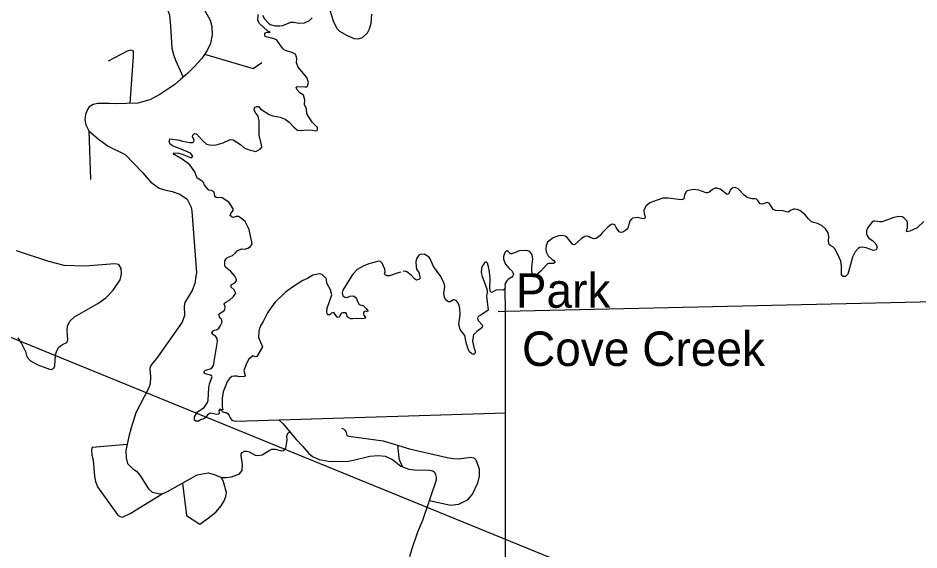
# Model space of a CAD drawing. Extents: x 1212896 to 1368412, y 378476 to 478763.
# Drawn here: x 1263202 to 1274256, y 408479 to 414998 of the extents above; entities that cross this region are included whole.
import ezdxf

# ---------------------------------------------------------------- set-up
doc = ezdxf.new("R2010")
doc.units = 0
for name, color, linetype in [('Level 31', 7, 'Continuous'), ('Level 32', 7, 'Continuous'), ('Level 45', 7, 'Continuous'), ('Level 46', 7, 'Continuous'), ('Level 5', 7, 'Continuous'), ('Level 60', 7, 'Continuous'), ('Level 7', 7, 'Continuous'), ('Level 9', 7, 'Continuous'), ('R_Draft', 7, 'Continuous')]:
    doc.layers.add(name, color=color, linetype=linetype)

msp = doc.modelspace()

# ---------------------------------------------------------------- linework, layer by layer
at = {"layer": 'Level 31'}
for points in [[(1265465, 415139), (1265558, 414972), (1265580, 414894), (1265583, 414791), (1265564, 414685), (1265521, 414599), (1265456, 414504), (1265365, 414399), (1265287, 414323), (1265195, 414246), (1265128, 414184), (1264944, 414060), (1264819, 413996), (1264672, 413955), (1264396, 413947), (1264326, 413952), (1264182, 413951), (1264125, 413938), (1264074, 413908), (1264053, 413878), (1264030, 413818), (1264021, 413752), (1264035, 413688), (1264073, 413617), (1264190, 413512), (1264308, 413426), (1264517, 413324), (1264729, 413106), (1264830, 412985), (1264933, 412912), (1265001, 412892), (1265092, 412873), (1265187, 412838), (1265278, 412779), (1265327, 412680), (1265336, 412631), (1265392, 411874), (1265382, 411833)], [(1265382, 411833), (1265370, 411745), (1265339, 411658), (1265247, 411513), (1265242, 411467), (1265244, 411351), (1265216, 411272), (1264912, 410841), (1264842, 410757), (1264827, 410733), (1264821, 410705), (1264829, 410599), (1264824, 410511), (1264805, 410458), (1264649, 410160), (1264589, 409978), (1264561, 409869), (1264527, 409699), (1264528, 409607), (1264547, 409539), (1264610, 409475), (1264654, 409444), (1264705, 409383), (1264805, 409230), (1264850, 409186), (1264925, 409172), (1264969, 409169), (1265038, 409196), (1265399, 409399), (1265535, 409426), (1265608, 409403), (1265698, 409368), (1265756, 409368), (1265823, 409376), (1265921, 409413), (1265954, 409452), (1265958, 409526), (1265941, 409638), (1265942, 409655), (1265952, 409673), (1265980, 409688), (1266002, 409692), (1266040, 409681), (1266112, 409639), (1266153, 409637), (1266196, 409645), (1266282, 409698), (1266318, 409713), (1266358, 409716), (1266435, 409693), (1266464, 409700), (1266487, 409725), (1266503, 409824), (1266501, 409873), (1266514, 409909), (1266536, 409926)], [(1266403, 410074), (1266454, 410024), (1266613, 409835), (1266695, 409749), (1266772, 409660), (1266814, 409624), (1266898, 409586), (1267032, 409565), (1267253, 409569), (1267319, 409579), (1267517, 409630), (1267620, 409635), (1267706, 409630), (1267798, 409589), (1267898, 409505), (1267996, 409468), (1268068, 409460), (1268250, 409459), (1268292, 409450), (1268312, 409432), (1268325, 409405), (1268333, 409371), (1268331, 409334), (1268166, 408840), (1268102, 408699), (1268032, 408495), (1268004, 408394)]]:
    msp.add_lwpolyline(points, dxfattribs=at)
at = {"layer": 'Level 32'}
for points in [[(1264942, 415255), (1265006, 415172), (1265042, 415095), (1265061, 415035), (1265075, 414902), (1265091, 414630), (1265110, 414553), (1265136, 414483), (1265230, 414275)], [(1264311, 414474), (1264547, 414596), (1264590, 414610), (1264614, 414595), (1264614, 414532), (1264576, 413952)], [(1264073, 413617), (1264090, 413020)], [(1264541, 409772), (1264113, 409734), (1264104, 409706), (1264109, 409641), (1264123, 409581), (1264140, 409381), (1264154, 409318), (1264176, 409252), (1264428, 408905), (1264456, 408890), (1264486, 408883), (1264578, 408926), (1264969, 409169)], [(1265220, 409298), (1265270, 408903), (1265431, 408794), (1265535, 408869), (1265628, 408942), (1265694, 409020), (1265732, 409080), (1265753, 409134), (1265759, 409183), (1265724, 409313), (1265698, 409368)]]:
    msp.add_lwpolyline(points, dxfattribs=at)
at = {"layer": 'Level 45'}
for points in [[(1265490, 414555), (1266088, 414378), (1266193, 414454)], [(1267172, 409970), (1267195, 409962), (1267211, 409949), (1267223, 409933), (1267237, 409883), (1267262, 409873), (1267684, 409815), (1268006, 409717), (1268468, 409612), (1268539, 409601), (1268605, 409598), (1268758, 409616), (1268795, 409607), (1268818, 409584), (1268858, 409473), (1268858, 409383), (1268839, 409296), (1268780, 409169), (1268711, 409088), (1268605, 409035), (1268511, 409024), (1268247, 409080)], [(1267856, 409762), (1267876, 409610), (1267888, 409568), (1267918, 409497)]]:
    msp.add_lwpolyline(points, dxfattribs=at)
at = {"layer": 'Level 46'}
msp.add_lwpolyline([(1263201, 411081), (1263244, 411011), (1263292, 410912), (1263312, 410848), (1263357, 410796), (1263444, 410750), (1263587, 410696), (1263611, 410692), (1263641, 410707), (1263655, 410734), (1263663, 410870), (1263679, 410921), (1263703, 410963), (1263746, 410998), (1263802, 411023), (1263815, 411053), (1263807, 411170), (1263808, 411221), (1263839, 411285), (1263897, 411338), (1264182, 411498), (1264278, 411570), (1264371, 411664), (1264457, 411790), (1264471, 411865), (1264468, 411928), (1264438, 411978), (1264390, 411986), (1264028, 411956), (1263769, 411966), (1263582, 412013), (1263183, 412145)], dxfattribs=at)
at = {"layer": 'Level 5'}
for points in [[(1274449, 411522), (1269181, 411401), (1269094, 411398)], [(1269182, 406131), (1269181, 410159)]]:
    msp.add_lwpolyline(points, dxfattribs=at)
at = {"layer": 'Level 60'}
msp.add_spline([(1275538, 388463), (1274493, 424373), (1274106, 437641)], degree=3, dxfattribs=at)
at = {"layer": 'Level 7'}
for points in [[(1269181, 410159), (1269181, 411401), (1269177, 411692)], [(1265680, 410203), (1265714, 410174), (1265727, 410166), (1265742, 410164), (1265754, 410163), (1265766, 410159), (1265779, 410148), (1265789, 410135), (1265794, 410122), (1265798, 410114), (1265807, 410097), (1265818, 410082), (1265827, 410072), (1265850, 410063), (1265880, 410058), (1269181, 410159)]]:
    msp.add_lwpolyline(points, dxfattribs=at)
at = {"layer": 'Level 9'}
for points in [[(1267009, 415160), (1267067, 414965), (1267115, 414870), (1267145, 414837), (1267239, 414786), (1267327, 414748), (1267378, 414743), (1267429, 414761), (1267488, 414817), (1267513, 414867), (1267536, 414935), (1267543, 415045)], [(1265359, 413486), (1265365, 413502), (1265342, 413546), (1265349, 413561), (1265369, 413582), (1265394, 413579), (1265464, 413496), (1265513, 413454), (1265573, 413440), (1265633, 413443), (1265719, 413470), (1265806, 413511), (1265841, 413505), (1265933, 413449), (1265978, 413409), (1266039, 413383), (1266119, 413363), (1266176, 413396), (1266194, 413417), (1266191, 413446), (1266160, 413564), (1266159, 413735), (1266147, 413796), (1266113, 413846), (1266100, 413874), (1266105, 413900), (1266131, 413914), (1266154, 413913), (1266180, 413881), (1266283, 413817), (1266329, 413798), (1266417, 413782), (1266481, 413760), (1266530, 413723), (1266587, 413661), (1266632, 413624), (1266672, 413619), (1266747, 413629), (1266815, 413625), (1266855, 413614), (1266875, 413626), (1266875, 413656), (1266812, 413721), (1266746, 413823), (1266740, 413884), (1266719, 413939), (1266721, 413997), (1266704, 414052), (1266659, 414083), (1266625, 414120), (1266616, 414149), (1266625, 414159), (1266720, 414155), (1266746, 414157), (1266754, 414163), (1266766, 414210), (1266744, 414270), (1266638, 414395), (1266618, 414448), (1266622, 414497), (1266610, 414551), (1266574, 414571), (1266470, 414606), (1266446, 414630), (1266379, 414726), (1266365, 414737), (1266315, 414753), (1266258, 414763), (1266235, 414773), (1266229, 414788), (1266231, 414806), (1266239, 414815), (1266258, 414824), (1266276, 414820), (1266294, 414825), (1266268, 414839), (1266166, 414930), (1266145, 414969)], [(1266145, 414969), (1266148, 415042)], [(1266202, 415035), (1266227, 414990), (1266274, 414934), (1266296, 414920), (1266358, 414902), (1266413, 414901), (1266452, 414906), (1266550, 414948), (1266587, 414946), (1266647, 414935), (1266719, 414939), (1266778, 414968), (1266813, 414999)], [(1265752, 411517), (1265796, 411542), (1265845, 411585), (1265874, 411625), (1265856, 411666), (1265816, 411700), (1265818, 411730), (1265863, 411754), (1265883, 411776), (1265881, 411793), (1265863, 411833), (1265815, 411891), (1265747, 411946), (1265740, 411962), (1265739, 412023), (1265754, 412049), (1265772, 412064), (1265834, 412089), (1265872, 412119), (1265892, 412144), (1265945, 412169), (1265985, 412164), (1266020, 412178), (1266054, 412197), (1266073, 412231), (1266037, 412405), (1265987, 412503), (1265933, 412551), (1265907, 412565), (1265879, 412564), (1265845, 412554), (1265828, 412559), (1265805, 412577), (1265815, 412604), (1265841, 412641), (1265840, 412661), (1265815, 412705), (1265787, 412742), (1265705, 412793), (1265634, 412799), (1265616, 412813), (1265614, 412849), (1265605, 412867), (1265578, 412885), (1265545, 412889), (1265490, 412948), (1265479, 412981), (1265460, 412997), (1265402, 413034), (1265372, 413114), (1265309, 413199), (1265217, 413267), (1265118, 413326), (1265110, 413338), (1265113, 413347), (1265171, 413342), (1265217, 413330), (1265320, 413288), (1265334, 413290), (1265346, 413305), (1265319, 413343), (1265202, 413393), (1265157, 413406), (1265106, 413430), (1265067, 413454), (1265056, 413486), (1265064, 413518), (1265182, 413503), (1265221, 413488), (1265311, 413471), (1265345, 413472), (1265359, 413486)], [(1273067, 412452), (1273009, 412481), (1272960, 412491), (1272937, 412501), (1272899, 412539), (1272861, 412588), (1272795, 412638), (1272763, 412652), (1272732, 412656), (1272715, 412655), (1272679, 412641), (1272659, 412624), (1272647, 412621), (1272584, 412637), (1272495, 412639), (1272467, 412650), (1272422, 412725), (1272398, 412737), (1272379, 412735), (1272331, 412716), (1272307, 412723), (1272280, 412764), (1272262, 412777), (1272245, 412781), (1272210, 412781), (1272148, 412799), (1272110, 412829), (1272038, 412906), (1272000, 412920), (1271972, 412918), (1271955, 412911), (1271939, 412888), (1271920, 412839), (1271903, 412834), (1271815, 412903), (1271775, 412915), (1271755, 412912), (1271721, 412897), (1271678, 412862), (1271663, 412857), (1271645, 412857), (1271554, 412888), (1271487, 412895), (1271449, 412890), (1271412, 412879), (1271401, 412870), (1271380, 412833), (1271372, 412783), (1271359, 412773), (1271338, 412770), (1271180, 412792), (1271113, 412792), (1270986, 412747), (1270955, 412732), (1270909, 412697), (1270883, 412653), (1270879, 412638), (1270883, 412604), (1270889, 412589)], [(1270889, 412589), (1270896, 412552), (1270891, 412540), (1270868, 412536), (1270800, 412552), (1270778, 412551), (1270743, 412544), (1270728, 412534), (1270705, 412505), (1270682, 412418), (1270661, 412397), (1270623, 412374), (1270602, 412369), (1270577, 412377), (1270540, 412430), (1270523, 412464), (1270499, 412472), (1270480, 412467), (1270444, 412439), (1270368, 412366), (1270343, 412335), (1270313, 412307), (1270294, 412297), (1270268, 412294), (1270221, 412308), (1270200, 412320), (1270177, 412325), (1270155, 412322), (1270115, 412297), (1270030, 412220), (1270009, 412222), (1269939, 412307), (1269917, 412326), (1269879, 412332), (1269833, 412328), (1269766, 412304), (1269700, 412253), (1269680, 412209), (1269676, 412163), (1269683, 412133), (1269708, 412085), (1269754, 412039), (1269777, 412025), (1269787, 412012), (1269788, 412002), (1269773, 411991), (1269716, 411992), (1269698, 411985), (1269680, 411969), (1269618, 411898), (1269561, 411846)], [(1274317, 412505), (1274235, 412426), (1274144, 412385), (1274107, 412379), (1274101, 412391), (1274115, 412433), (1274114, 412494), (1274106, 412511), (1274069, 412551), (1274051, 412560), (1274009, 412564), (1273947, 412554), (1273806, 412501), (1273771, 412499), (1273714, 412510), (1273699, 412510), (1273683, 412502), (1273623, 412424), (1273611, 412390), (1273612, 412359), (1273619, 412331), (1273642, 412299), (1273686, 412272), (1273712, 412249), (1273725, 412229), (1273735, 412210), (1273741, 412184), (1273729, 412156), (1273696, 412150), (1273608, 412183), (1273557, 412191), (1273529, 412185), (1273511, 412173), (1273473, 412133), (1273439, 412068), (1273393, 411886), (1273382, 411858), (1273353, 411829), (1273324, 411831), (1273304, 411848), (1273304, 411961), (1273298, 412018), (1273266, 412092), (1273225, 412171), (1273200, 412196), (1273174, 412208), (1273155, 412223), (1273147, 412262), (1273151, 412321), (1273142, 412366), (1273109, 412414), (1273067, 412452)], [(1268894, 411365), (1268857, 411346), (1268845, 411331), (1268841, 411315), (1268849, 411293), (1268896, 411240), (1268902, 411225), (1268893, 411201), (1268833, 411156), (1268792, 411117), (1268785, 411095), (1268779, 411040), (1268797, 410945), (1268809, 410918), (1268811, 410900), (1268807, 410886), (1268791, 410875), (1268768, 410882), (1268740, 410907), (1268719, 410954), (1268699, 411020), (1268684, 411108), (1268626, 411180), (1268610, 411243), (1268626, 411367), (1268624, 411438), (1268615, 411476), (1268599, 411514), (1268578, 411536), (1268565, 411542), (1268544, 411543), (1268503, 411522), (1268483, 411522), (1268452, 411539), (1268433, 411577), (1268428, 411623), (1268439, 411709), (1268431, 411746), (1268389, 411830), (1268300, 411953), (1268258, 412049), (1268246, 412067), (1268184, 412106), (1268140, 412101), (1268118, 412093), (1268094, 412054), (1268083, 412016), (1268083, 411997), (1268092, 411919), (1268120, 411880), (1268133, 411827), (1268134, 411809), (1268120, 411792), (1268090, 411786), (1268067, 411802), (1268024, 411848), (1267972, 411889), (1267946, 411897), (1267926, 411893)], [(1269561, 411846), (1269538, 411827), (1269522, 411825), (1269511, 411833), (1269507, 411947), (1269520, 412045), (1269509, 412095), (1269481, 412137), (1269443, 412148), (1269352, 412145), (1269292, 412119), (1269257, 412109), (1269246, 412110), (1269206, 412144), (1269196, 412145), (1269176, 412123), (1269158, 412074), (1269160, 412044), (1269185, 411980), (1269225, 411931), (1269264, 411894), (1269273, 411881), (1269280, 411856), (1269273, 411839), (1269260, 411823), (1269218, 411796), (1269201, 411779), (1269180, 411744), (1269176, 411723), (1269180, 411698), (1269174, 411682), (1269156, 411664), (1269073, 411669), (1269015, 411635), (1269000, 411642), (1268989, 411682), (1268993, 411809), (1268983, 411918), (1268975, 411951), (1268961, 411994), (1268950, 412006), (1268937, 412005), (1268927, 411998), (1268901, 411960), (1268887, 411932), (1268883, 411879), (1268896, 411830), (1268927, 411756), (1268958, 411662), (1268958, 411640), (1268948, 411588), (1268971, 411420), (1268894, 411365)], [(1267898, 411883), (1267853, 411873), (1267759, 411840), (1267731, 411840), (1267706, 411851), (1267700, 411866), (1267706, 411886), (1267703, 411922), (1267668, 411996), (1267649, 412014), (1267630, 412017), (1267506, 411984), (1267438, 411958), (1267363, 411916), (1267313, 411865), (1267293, 411836), (1267187, 411664), (1267181, 411632), (1267189, 411594), (1267210, 411579), (1267241, 411575), (1267275, 411589), (1267306, 411593), (1267325, 411590), (1267352, 411569), (1267372, 411515), (1267388, 411489), (1267440, 411471), (1267473, 411438), (1267493, 411408), (1267491, 411398), (1267463, 411404), (1267449, 411400), (1267440, 411383), (1267444, 411357), (1267466, 411330), (1267464, 411319), (1267433, 411312), (1267379, 411317), (1267308, 411310), (1267285, 411312), (1267263, 411318), (1267240, 411336), (1267238, 411369), (1267224, 411385), (1267187, 411387), (1267172, 411382), (1267162, 411372), (1267151, 411346), (1267140, 411332), (1267123, 411330)], [(1267123, 411330), (1267113, 411336), (1267078, 411388), (1267062, 411387), (1267049, 411380), (1267026, 411359), (1267009, 411359), (1266998, 411366), (1266991, 411396), (1266997, 411443), (1267051, 411608), (1267035, 411667), (1266993, 411748), (1266988, 411790), (1266981, 411807), (1266932, 411856), (1266902, 411863), (1266880, 411860), (1266818, 411847), (1266753, 411807), (1266697, 411782), (1266559, 411692), (1266478, 411633), (1266359, 411516), (1266318, 411462), (1266263, 411385), (1266209, 411278), (1266177, 411226), (1266166, 411195)], [(1266166, 411195), (1266156, 411157), (1266151, 411083), (1266201, 410970), (1266133, 410851), (1266118, 410848), (1266085, 410858), (1266035, 410816), (1266008, 410774), (1265971, 410680), (1265990, 410617), (1265979, 410605), (1265916, 410602), (1265892, 410609), (1265859, 410609), (1265827, 410604), (1265796, 410580), (1265774, 410549), (1265758, 410519), (1265721, 410418), (1265708, 410340), (1265706, 410232), (1265713, 410199), (1265706, 410197), (1265680, 410203), (1265667, 410189), (1265669, 410154), (1265664, 410145), (1265643, 410141), (1265566, 410154), (1265551, 410152), (1265522, 410127), (1265505, 410103), (1265483, 410088), (1265442, 410073), (1265420, 410059), (1265385, 410058), (1265369, 410072), (1265368, 410110), (1265404, 410171), (1265486, 410226), (1265527, 410286), (1265536, 410315), (1265543, 410467), (1265551, 410514), (1265586, 410602), (1265581, 410610), (1265562, 410621), (1265516, 410633), (1265488, 410648), (1265486, 410666), (1265501, 410682), (1265574, 410704), (1265601, 410740), (1265651, 411035), (1265645, 411071), (1265626, 411100), (1265600, 411114), (1265581, 411142), (1265589, 411162), (1265613, 411174), (1265639, 411175), (1265661, 411190), (1265683, 411220), (1265706, 411271), (1265697, 411307), (1265679, 411324), (1265664, 411363), (1265683, 411382), (1265716, 411400), (1265738, 411423), (1265745, 411463), (1265732, 411490), (1265734, 411504), (1265752, 411517)]]:
    msp.add_lwpolyline(points, dxfattribs=at)
at = {"layer": 'R_Draft'}
msp.add_line((1253662, 414939), (1283026, 402970), dxfattribs=at)

# ---------------------------------------------------------------- texts
at = {"layer": 'Level 45'}
msp.add_text('Park', height=422.4, dxfattribs=at).set_placement((1269309, 411448))
at = {"layer": 'Level 7'}
msp.add_text('Cove Creek', height=422.4, dxfattribs=at).set_placement((1269385, 410734))

doc.saveas('drawing.dxf')
